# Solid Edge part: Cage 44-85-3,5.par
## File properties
Title: Thrust Bearing Cage
Author: Dan
Comments: R2-05
Template: Normal.par
Last saved by: Dan
Revision: 39
Application: Solid Edge
Density: 1.2 kg/dm^3
Accuracy: 0.99
Document Number: P52-004-4
Project Name: Piston Pump P52
Material: ptfe nylon
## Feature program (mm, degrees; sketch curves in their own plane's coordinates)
sketch for "unnamed Protrusion 1" #1 plane through (0, 0, 0) normal (0, 0, 1) x-axis (1, 0, 0)
  circle centre (0, 0) radius 22.2
sketch for "unnamed Protrusion 1" #2 plane through (0, 0, 0) normal (0, 0, 1) x-axis (1, 0, 0)
  circle centre (0, 0) radius 43.5
extrude "unnamed Protrusion 1" add finite 3.69 along +normal
sketch for "ExtrudedCutout_1" plane through (0, -40.5, 0) normal (0, -1, 0) x-axis (1, 0, 0)
extrude "ExtrudedCutout_1" cut finite 16.4 along -normal  Plane_Distance = 40.5 mm
pattern "unnamed Pattern 1" of "ExtrudedCutout_1"
extrude "unnamed Cutout 1" cut finite 16.4
extrude "unnamed Cutout 2" cut finite 16.4
extrude "unnamed Cutout 3" cut finite 16.4
extrude "unnamed Cutout 4" cut finite 16.4
extrude "unnamed Cutout 5" cut finite 16.4
extrude "unnamed Cutout 6" cut finite 16.4
extrude "unnamed Cutout 7" cut finite 16.4
extrude "unnamed Cutout 8" cut finite 16.4
extrude "unnamed Cutout 9" cut finite 16.4
extrude "unnamed Cutout 10" cut finite 16.4
extrude "unnamed Cutout 11" cut finite 16.4
extrude "unnamed Cutout 12" cut finite 16.4
extrude "unnamed Cutout 13" cut finite 16.4
extrude "unnamed Cutout 14" cut finite 16.4
extrude "unnamed Cutout 15" cut finite 16.4
extrude "unnamed Cutout 16" cut finite 16.4
extrude "unnamed Cutout 17" cut finite 16.4
chamfer "Chamfer_2" setback 2  SetBackValue2 = 17 deg
sketch for "unnamed RevolvedProtrusion 1" plane through (0, 0, 0) normal (0, -1, 0) x-axis (1, 0, 0)
  line (43.5, -1) -> (41.5, -1)
  line (41.5, -1) -> (41.5, 4.69)
  line (41.5, 4.69) -> (42.5828, 4.69)
  line (43.5, 1.69) -> (42.5828, 4.69)
  line (43.5, -1) -> (43.5, 1.69)
  dimension (linear) = 43.5
revolve "unnamed RevolvedProtrusion 1" add full turn 360 deg
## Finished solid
Body 1: solid body, 117 faces, 333 edges, 216 vertices.
  Faces by surface: plane 76, cylinder 40, cone 1
  Edges by curve: line 252, circle 81
Bounding box of the edges (mm): 87.000 x 87.000 x 5.690, from (-43.5, -43.5, -1) to (43.5, 43.5, 4.69).
Cylindrical faces by radius (mm): R2.65 x36, R22.2 x1, R41.5 x2, R43.5 x1
Conical faces (half-angle, radius in mm at the cone's reference point): 17 deg R43.5 x1
Planar faces by outward normal: +y 2, +z 2, -y 2, -z 2, oblique 68
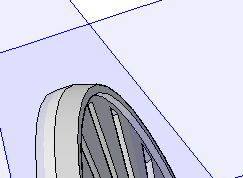
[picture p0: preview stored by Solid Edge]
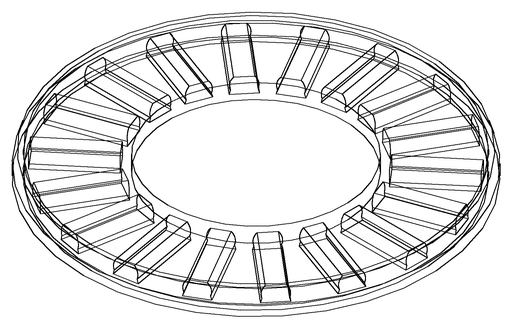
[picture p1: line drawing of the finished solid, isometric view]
